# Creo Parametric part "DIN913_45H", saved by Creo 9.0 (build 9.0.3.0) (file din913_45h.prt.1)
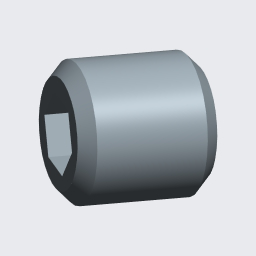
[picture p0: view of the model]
Units: millimeter Newton Second (mmNs); MM, TONNE, SECS
Materials in the file: STAHL

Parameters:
  PLACEMENT = "A"
  BENENNUNG = "din913_45h.prt"
  WERKSTOFF = "xxx"
  OBERFLAECHE = "xxx"
  ERSTELLER = "CE-SYS"
  PTC_MATERIAL_NAME = "STAHL"

Other parameters: THREADS_PER_INCH, MASSE, D9, D6, D17, D16

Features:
  1. coordinate system
  2. datum plane "VORNE_X-Y"
  3. datum plane "OBEN_X-Z"
  4. datum plane "RECHTS_Y-Z"
  5. datum point "PNT0"
  6. datum axis
  7. datum axis
  8. datum axis
  9. protrusion
  10. cut
  11. cut
  12. chamfer

Other named items: A_Y, A_X, A_Z, CS0

Named dimensions: Durchmesser, Sechskanttiefe, Fasengroesse, Kerndurchmesser

Layers: ACHSEN, ALLE, EBENEN, GEWINDE, KOORDSYS, PUNKTE, SAMMELFLÄCHEN, VOLUMENGEOMETRIE

Family table entries: DIN913_45H_M2X2, DIN913_45H_M2x2, DIN913_45H, value(d_val), value(s_val), DIN913_45H_M2x2, value(i_val), DIN913_45H_M2X3, DIN913_45H_M2x3, DIN913_45H, )DIN913_45H_M2x3, DIN913_45H_M2X4, DIN913_45H_M2x4, DIN913_45H, )DIN913_45H_M2x4, DIN913_45H_M2X5, DIN913_45H_M2x5, DIN913_45H, )DIN913_45H_M2x5, DIN913_45H_M2X6, DIN913_45H_M2x6, DIN913_45H, )DIN913_45H_M2x6, DIN913_45H_M2X8, DIN913_45H_M2x8, DIN913_45H, 2/ , )DIN913_45H_M2x8, DIN913_45H_M2X10, DIN913_45H_M2x10, DIN913_45H, 2/$, )DIN913_45H_M2x10, DIN913_45H_M2_5X4, DIN913_45H_M2,5x4, DIN913_45H, )DIN913_45H_M2,5x4, DIN913_45H_M2_5X5, DIN913_45H_M2,5x5, DIN913_45H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

Surfaces: 14 plane, 8 cone, 2 cylinder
